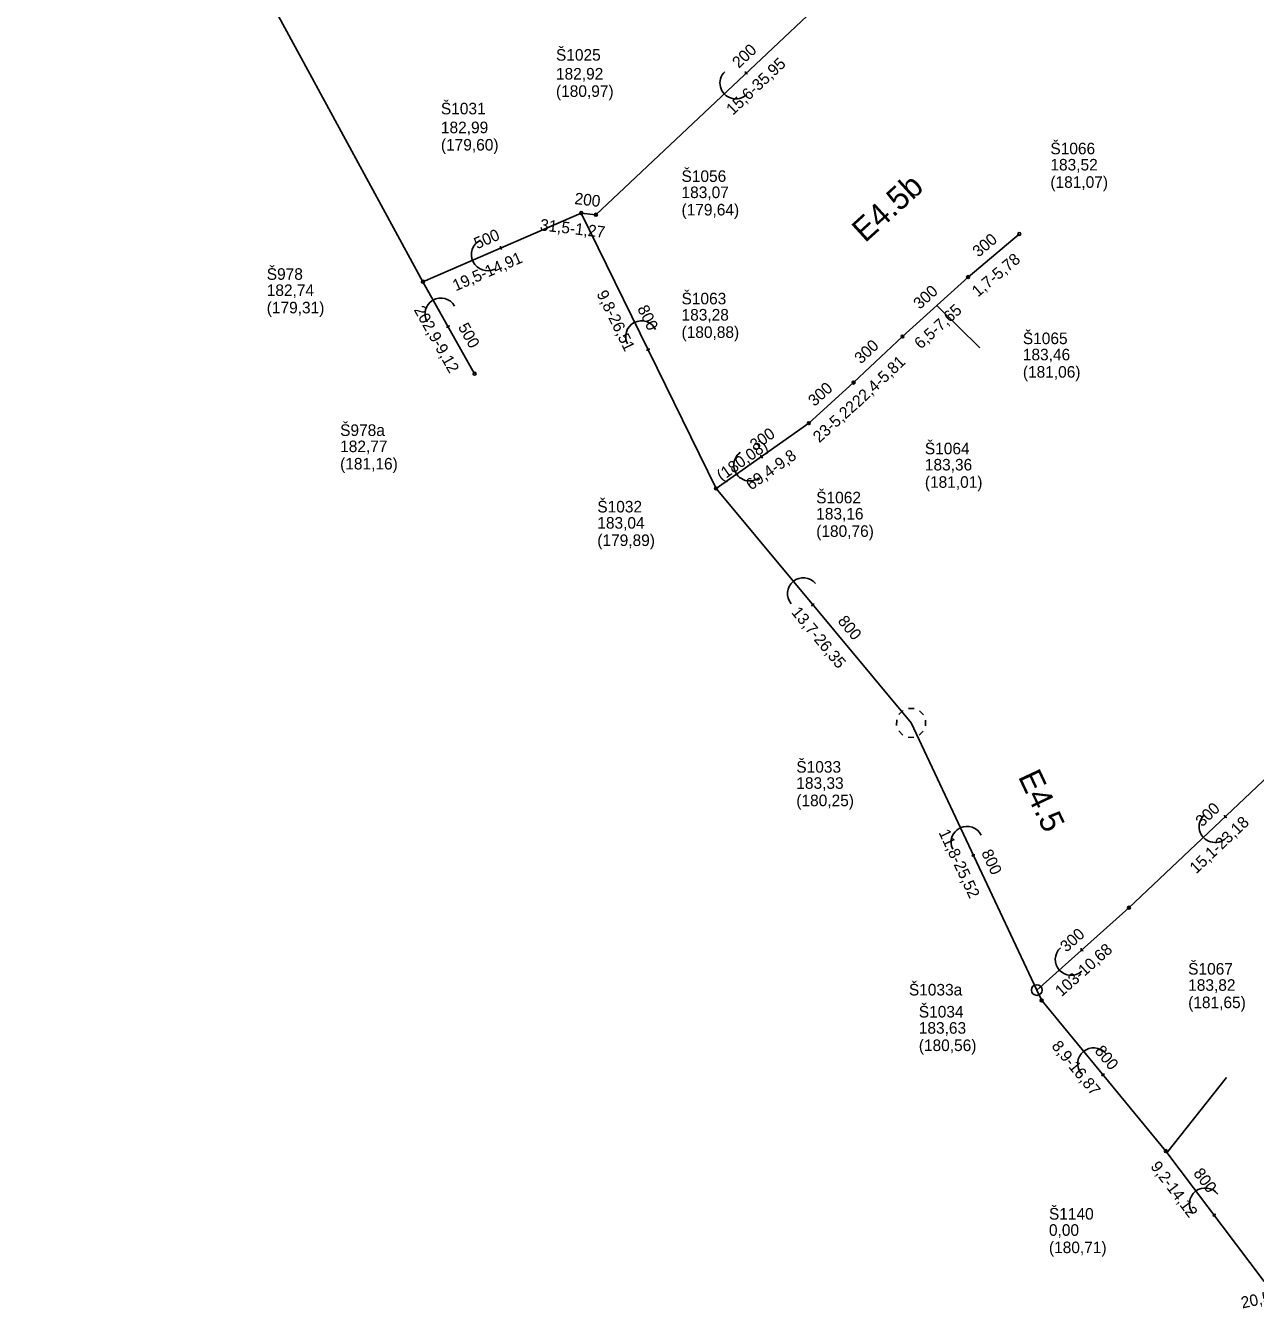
# Model space of a CAD drawing. Extents: x -548529 to -543591, y -1201432 to -1192608.
# Drawn here: x -544440.1 to -544333.8, y -1194060.3 to -1193949.5 of the extents above; entities that cross this region are included whole.
import ezdxf

# ---------------------------------------------------------------- set-up
doc = ezdxf.new("R2010")
doc.units = 0
for name, color, linetype in [('C3D_Bod-Značky', 7, 'Continuous'), ('C3D_Koridor', 7, 'Continuous'), ('C3D_Křižovatka', 7, 'Continuous'), ('C3D_Netisknutelná', 7, 'Continuous'), ('C3D_PP-zobrazeni v PR', 7, 'Continuous'), ('C3D_PR-Popisek', 7, 'Continuous'), ('C3D_SPR-Popisek', 7, 'Continuous'), ('C3D_Tlakove_potrubi_Popis', 7, 'Continuous'), ('C3D_ZPR-Formaty', 7, 'Continuous')]:
    doc.layers.add(name, color=color, linetype=linetype)

# ---------------------------------------------------------------- blocks, each defined once
blk = doc.blocks.new('100')
at = {"layer": 'Defpoints'}
blk.add_circle((0, 0), 0.127, dxfattribs=at)
blk = doc.blocks.new('102')
at = {"layer": 'Defpoints'}
for p, q in [((-0.49, 1.17), (0, 1.27)), ((0.49, 1.17), (0.9, 0.9)), ((-1.17, -0.49), (-1.27, 0)), ((-1.17, 0.49), (-0.9, 0.9)), ((1.17, 0.49), (1.27, 0)), ((-0.49, -1.17), (-0.9, -0.9)), ((1.17, -0.49), (0.9, -0.9)), ((0.49, -1.17), (0, -1.27))]:
    blk.add_line(p, q, dxfattribs=at)
blk = doc.blocks.new('101')
at = {"layer": 'Defpoints'}
blk.add_circle((0, 0), 0.463, dxfattribs=at)
blk = doc.blocks.new('91')
at = {"layer": 'Defpoints'}
blk.add_lwpolyline([(0.08, 0.14), (0.19, 0), (0.08, -0.14)], dxfattribs=at)
blk.add_arc((1.37, 0), 1.37, 270, 90, dxfattribs=at)

msp = doc.modelspace()

# ---------------------------------------------------------------- linework, layer by layer
at = {"layer": 'C3D_Bod-Značky'}
for points in [[(-544405.73, -1193971.59), (-544440.067, -1193908.361)], [(-544364.634, -1193941.139), (-544390.782, -1193965.807)], [(-544392.047, -1193965.657), (-544405.73, -1193971.59)], [(-544390.782, -1193965.807), (-544392.047, -1193965.657)], [(-544380.39, -1193989.47), (-544392.047, -1193965.657)], [(-544354.19, -1193967.47), (-544358.61, -1193971.19)], [(-544401.267, -1193979.545), (-544405.73, -1193971.59)], [(-544358.61, -1193971.19), (-544364.28, -1193976.33)], [(-544364.28, -1193976.33), (-544368.51, -1193980.31)], [(-544368.51, -1193980.31), (-544372.38, -1193983.82)], [(-544372.38, -1193983.82), (-544380.39, -1193989.47)], [(-544363.54, -1194009.73), (-544380.39, -1193989.47)], [(-544352.679, -1194032.821), (-544363.54, -1194009.73)], [(-544327.866, -1194009.782), (-544344.712, -1194025.708)], [(-544344.712, -1194025.708), (-544352.679, -1194032.821)], [(-544352.253, -1194033.726), (-544352.679, -1194032.821)], [(-544341.525, -1194046.745), (-544352.253, -1194033.726)], [(-544333.011, -1194058.013), (-544341.525, -1194046.745)]]:
    msp.add_lwpolyline(points, dxfattribs=at)
at = {"layer": 'C3D_Koridor'}
for points in [[(-544361.317, -1193973.644), (-544357.612, -1193977.309)], [(-544341.423, -1194046.881), (-544336.281, -1194040.38)]]:
    msp.add_lwpolyline(points, dxfattribs=at)

# ---------------------------------------------------------------- block references
at = {"layer": 'C3D_PP-zobrazeni v PR'}
for name, p, xscale, yscale, rotation in [('100', (-544392.047, -1193965.657), 1.0296949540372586, 1.0296949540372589, 155.86620948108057), ('100', (-544390.782, -1193965.807), 1.0316957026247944, 1.0316957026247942, -156.4154111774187), ('100', (-544354.19, -1193967.47), 1.0000000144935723, 1.0000000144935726, 40.99999910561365), ('100', (-544405.73, -1193971.59), 1.0000000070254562, 1.0000000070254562, 118.99999892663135), ('100', (-544358.61, -1193971.19), 1.0000000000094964, 1.0000000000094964, -137.9999986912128), ('100', (-544364.28, -1193976.33), 1.00000000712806, 1.00000000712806, -136.99999943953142), ('100', (-544401.267, -1193979.545), 1.0000000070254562, 1.0000000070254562, 118.99999892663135), ('100', (-544368.51, -1193980.31), 1.00000000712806, 1.00000000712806, -136.99999943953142), ('100', (-544372.38, -1193983.82), 1.000000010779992, 1.0000000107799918, -141.00000108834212), ('100', (-544380.39, -1193989.47), 1.0009848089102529, 1.000984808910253, 165.77567372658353), ('102', (-544363.54, -1194009.73), 0.9999999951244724, 0.9999999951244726, -56.999998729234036), ('100', (-544344.712, -1194025.708), 1.00000000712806, 1.00000000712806, 43.0000005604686), ('101', (-544352.679, -1194032.821), 1.0000000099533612, 1.0000000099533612, -63.999999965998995), ('100', (-544352.253, -1194033.726), 0.9999999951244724, 0.9999999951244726, -56.999998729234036), ('100', (-544341.525, -1194046.745), 1.000000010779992, 1.0000000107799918, -51.00000108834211)]:
    msp.add_blockref(name, p, dxfattribs=dict(at, xscale=xscale, yscale=yscale, rotation=rotation))
at = {"layer": 'C3D_SPR-Popisek'}
for p, xscale, yscale, rotation in [((-544377.708, -1193953.473), 1.0000000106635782, 1.0000000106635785, -135.99999834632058), ((-544398.888, -1193968.624), 1.019856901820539, 1.0198569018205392, -153.606016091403), ((-544403.498, -1193975.568), 0.9999999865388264, 0.9999999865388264, 120.00000044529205), ((-544386.218, -1193977.564), 0.9999999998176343, 0.9999999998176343, 116.9999993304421), ((-544376.385, -1193986.645), 1.000000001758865, 1.000000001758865, -144.00000066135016), ((-544371.965, -1193999.6), 1.0000000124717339, 1.0000000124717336, 130.0000013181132), ((-544336.289, -1194017.745), 1.0000000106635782, 1.0000000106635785, -135.99999834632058), ((-544358.109, -1194021.276), 1.0000000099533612, 1.0000000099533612, 116.000000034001), ((-544348.695, -1194029.265), 1.0000000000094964, 1.0000000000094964, -137.9999986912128), ((-544346.889, -1194040.236), 1.0000000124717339, 1.0000000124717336, 130.0000013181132), ((-544337.268, -1194052.379), 1.000000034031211, 1.0000000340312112, 128.00000040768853)]:
    msp.add_blockref('91', p, dxfattribs=dict(at, xscale=xscale, yscale=yscale, rotation=rotation))

# ---------------------------------------------------------------- texts
at = {"layer": 'C3D_Křižovatka'}
for s, p in [('Š1025', (-544394.232, -1193952.488)), ('Š1031', (-544404.177, -1193957.127)), ('Š1066', (-544351.5, -1193960.58)), ('Š1056', (-544383.382, -1193962.967)), ('Š978', (-544419.23, -1193971.43)), ('Š1063', (-544383.38, -1193973.55)), ('Š1065', (-544353.88, -1193976.99)), ('Š978a', (-544412.887, -1193984.925)), ('Š1064', (-544362.35, -1193986.51)), ('Š1032', (-544390.66, -1193991.54)), ('Š1062', (-544371.74, -1193990.75)), ('Š1033', (-544373.46, -1194014.03)), ('Š1067', (-544339.592, -1194031.488)), ('Š1033a', (-544363.729, -1194033.291)), ('Š1034', (-544362.873, -1194035.196)), ('Š1140', (-544351.625, -1194052.665))]:
    msp.add_text(s, height=1, dxfattribs=at).set_placement(p)
at = {"layer": 'C3D_Netisknutelná'}
for s, rotation, p in [('E4.5b', 42.19, (-544367.514, -1193968.278)), ('E4.5', 295.19, (-544354.319, -1194014.371))]:
    msp.add_text(s, height=2, rotation=rotation, dxfattribs=at).set_placement(p)
at = {"layer": 'C3D_PR-Popisek'}
for s, rotation, p in [('200', 43.33, (-544378.43, -1193953.198)), ('200', 353.24, (-544392.671, -1193964.874)), ('500', 23.44, (-544401.048, -1193968.796)), ('300', 40.08, (-544357.716, -1193969.526)), ('300', 42.19, (-544362.792, -1193974.032)), ('800', 296.08, (-544387.226, -1193973.911)), ('500', 299.29, (-544402.733, -1193975.498)), ('300', 43.26, (-544367.874, -1193978.758)), ('300', 42.21, (-544371.887, -1193982.425)), ('300', 35.2, (-544377.026, -1193986.239)), ('800', 309.75, (-544369.932, -1194000.954)), ('300', 43.39, (-544338.386, -1194018.771)), ('800', 295.19, (-544357.496, -1194020.944)), ('300', 41.76, (-544350.116, -1194029.605)), ('800', 309.49, (-544347.725, -1194038.113)), ('800', 307.08, (-544339.192, -1194048.671))]:
    msp.add_text(s, height=1, rotation=rotation, dxfattribs=at).set_placement(p)
at = {"layer": 'C3D_Tlakove_potrubi_Popis'}
for s, p in [('182,92 ', (-544394.232, -1193954.118)), ('(180,97)', (-544394.232, -1193955.618)), ('182,99 ', (-544404.177, -1193958.757)), ('(179,60)', (-544404.177, -1193960.257)), ('183,52 ', (-544351.5, -1193961.98)), ('(181,07)', (-544351.5, -1193963.48)), ('183,07 ', (-544383.382, -1193964.367)), ('(179,64)', (-544383.382, -1193965.867)), ('182,74 ', (-544419.23, -1193972.83)), ('(179,31)', (-544419.23, -1193974.33)), ('183,28 ', (-544383.38, -1193974.95)), ('(180,88)', (-544383.38, -1193976.45)), ('183,46 ', (-544353.88, -1193978.39)), ('(181,06)', (-544353.88, -1193979.89)), ('182,77 ', (-544412.887, -1193986.325)), ('(181,16)', (-544412.887, -1193987.825)), ('183,36 ', (-544362.35, -1193987.91)), ('(181,01)', (-544362.35, -1193989.41)), ('183,16 ', (-544371.74, -1193992.15)), ('183,04 ', (-544390.66, -1193992.94)), ('(180,76)', (-544371.74, -1193993.65)), ('(179,89)', (-544390.66, -1193994.44)), ('183,33 ', (-544373.46, -1194015.43)), ('(180,25)', (-544373.46, -1194016.93)), ('183,82 ', (-544339.592, -1194032.888)), ('(181,65)', (-544339.592, -1194034.388)), ('183,63 ', (-544362.873, -1194036.596)), ('(180,56)', (-544362.873, -1194038.096)), ('0,00 ', (-544351.625, -1194054.065)), ('(180,71)', (-544351.625, -1194055.565))]:
    msp.add_text(s, height=1, dxfattribs=at).set_placement(p)
at = {"layer": 'C3D_ZPR-Formaty'}
for s, rotation, p in [('15,6-35,95', 43.33, (-544378.941, -1193957.248)), ('31,5-1,27', 353.24, (-544395.657, -1193967.147)), ('19,5-14,91', 23.44, (-544402.901, -1193972.433)), ('1,7-5,78', 40.08, (-544357.766, -1193972.966)), ('9,8-26,51', 296.08, (-544390.75, -1193972.631)), ('202,9-9,12', 299.29, (-544406.545, -1193974.015)), ('6,5-7,65', 42.19, (-544362.708, -1193977.471)), ('22,4-5,81', 43.26, (-544368.061, -1193982.497)), ('23-5,22', 42.21, (-544371.47, -1193985.561)), ('  (180,08)   ', 35.2, (-544380.505, -1193989.307)), ('69,4-9,8', 35.2, (-544377.368, -1193989.66)), ('13,7-26,35', 309.75, (-544373.943, -1194000.198)), ('15,1-23,18', 43.39, (-544338.894, -1194022.822)), ('11,8-25,52', 295.19, (-544361.183, -1194019.2)), ('103-10,68', 41.76, (-544350.548, -1194033.457)), ('8,9-16,87', 309.49, (-544351.453, -1194037.69)), ('9,2-14,12', 307.08, (-544342.897, -1194048.081)), ('20,5-2,93', 11.9, (-544334.912, -1194060.349))]:
    msp.add_text(s, height=1, rotation=rotation, dxfattribs=at).set_placement(p)

doc.saveas('drawing.dxf')
